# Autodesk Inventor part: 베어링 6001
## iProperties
IsCustomPart: 1
Created: 2009-02
Part Number: 베어링 6001
Material: 강, 연강
Description: 깊은 그루브 볼 베어링
Document SubType Name: Modeling
Standard: KS B 2023
Standards Organization: KS
Language: ko-KR
Size Designation: 6001 - 12 x 28 x 8
Categories: <MemberInstance><Categories><Category DisplayName="샤프트 부품" InternalName="7f7aeb1f-a693-4053-b835-cee3144e0d98" Mnemonic="SHFT"><Category DisplayName="베어링" Inter
Density: 1 g/cm^3
Engineer: 한국산업디자인학원-SeoGD™
Author: 진현석
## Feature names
1. IDS_ARRAYBALL[SIMPL:T] [Circular Pattern]
